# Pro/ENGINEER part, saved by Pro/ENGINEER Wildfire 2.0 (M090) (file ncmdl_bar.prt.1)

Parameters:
  NCX_STOCK_TYPE = "BAR"

Other parameters: WP_Z, WP_D

Family table entries: PRO_MP_ALT_MASS, ~"x, PRO_MP_ALT_VOLUME, ~"x, PRO_MP_ALT_AREA, ~"x, PRO_MP_ALT_COGX, ~"x, PRO_MP_ALT_COGY, ~"x, PRO_MP_ALT_COGZ, ~"x, PRO_MP_ALT_IXX, ~"x, PRO_MP_ALT_IYY, ~"x, PRO_MP_ALT_IZZ, ~"x, PRO_MP_ALT_IXZ, ~"x, PRO_MP_ALT_IYZ, ~"x, PRO_MP_ALT_IXY, ~"x, PRO_MP_MASS, PRO_MP_VOLUME, PRO_MP_DENSITY, PRO_MP_AREA, PRO_MP_COGX, PRO_MP_COGY, PRO_MP_COGZ, PRO_MP_IXX, PRO_MP_IYY, PRO_MP_IZZ, PRO_MP_IXZ, PRO_MP_IYZ, PRO_MP_IXY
